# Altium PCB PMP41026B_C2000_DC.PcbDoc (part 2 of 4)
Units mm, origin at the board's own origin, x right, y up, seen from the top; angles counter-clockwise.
Board outline 100 x 30 mm, 4 copper layers (Top Layer, Layer2-Plane, Layer3-Plane, Bottom Layer), stack 1.565 mm thick; 260 components, 175 nets, 797 pads, 279 vias.
Unrouted connection lines stored in the file: 19.
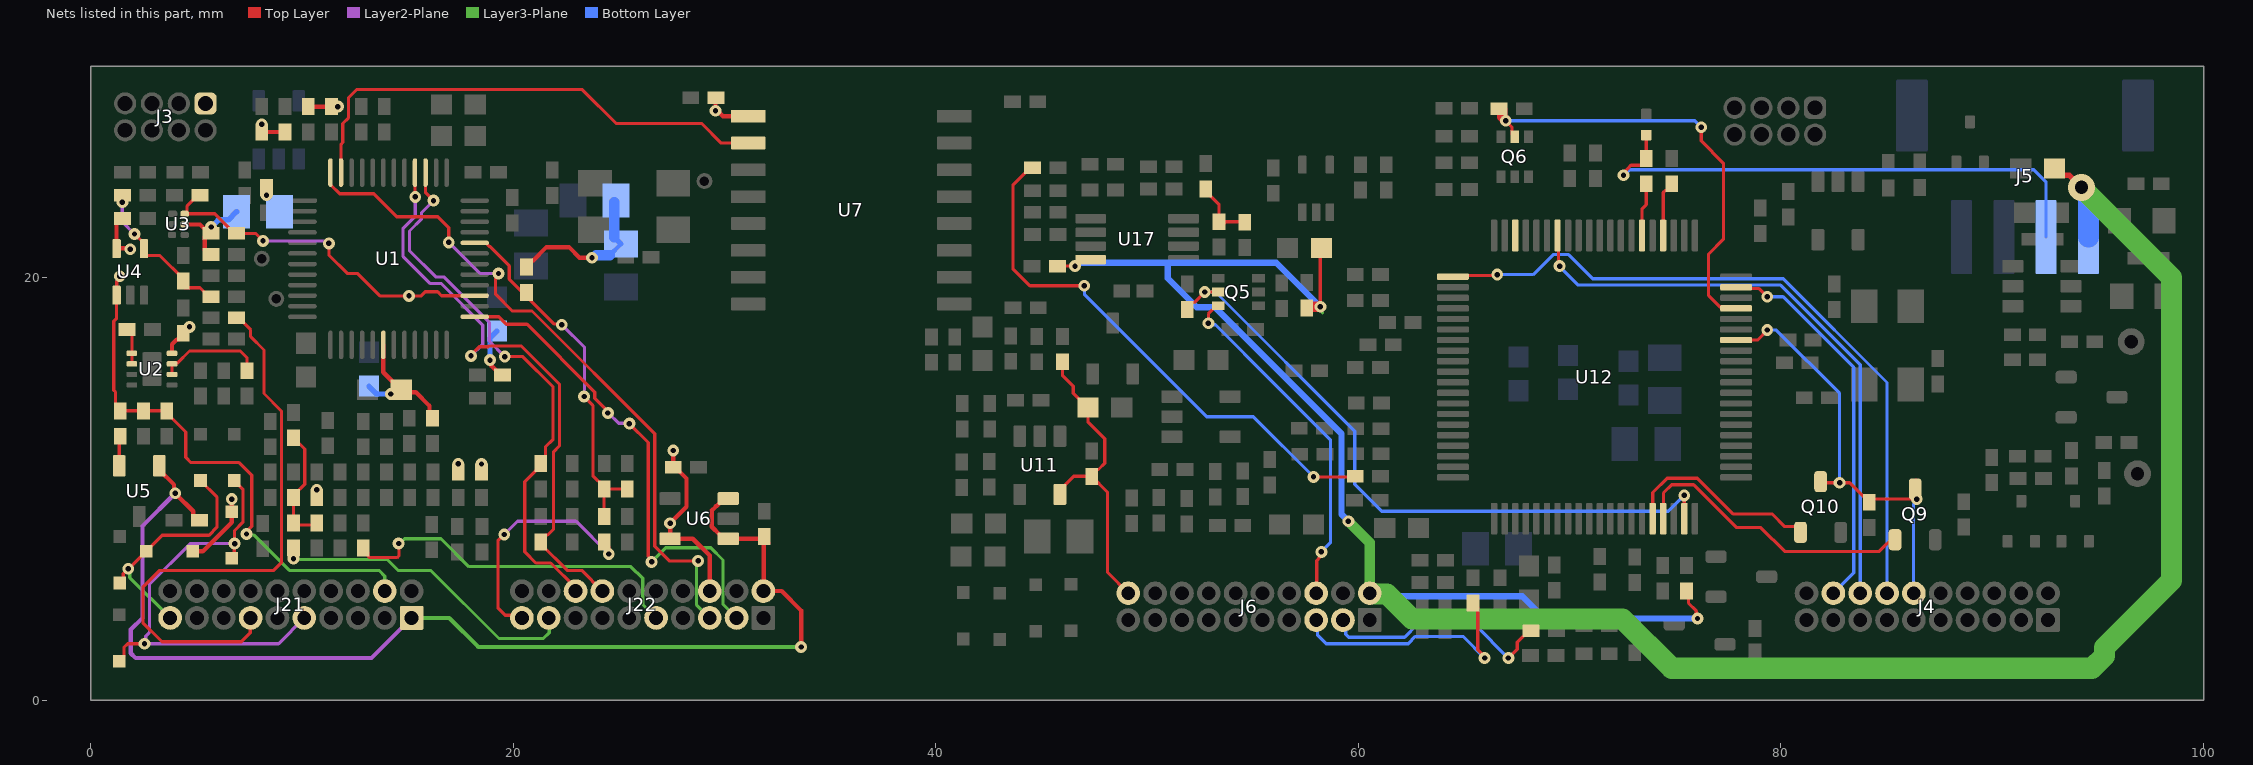
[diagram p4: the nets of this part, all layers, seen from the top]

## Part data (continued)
C2 C3 C4 C5 C71 C73 C74 C75 C76 C77 C79: library part CMP-0006320-2, "CAP, CERM, 470 pF, 50 V, +/- 10%, X7R, AEC-Q200 Grade 1, 0402", Cap_Case=0402, Manufacturer=TDK, Supplier Part Number 1=445-6888-1-ND, TempCo=X7R, Tolerance_%=10%, Value1="4.96489 ohm", Value2=50V, ValueDisplayed=470pF
C6 C9 C14 C15: library part CMP-0006531-2, "CAP, CERM, 0.1 uF, 6.3 V, +/- 10%, X5R, 0402", Cap_Case=0402, Manufacturer=MuRata, Supplier Part Number 1=GRM155R60J104KA01D-ND, TempCo=X5R, Tolerance_%=10%, Value1=Unknown, Value2=6.3V, ValueDisplayed=0.1uF
C7: library part CMP-0006266-2, "CAP, CERM, 0.047 uF, 10 V, +/- 10%, X5R, 0402", Cap_Case=0402, Manufacturer=TDK, Supplier Part Number 1=445-4980-1-ND, TempCo=X5R, Tolerance_%=10%, Value1=Unknown, Value2=10V, ValueDisplayed=0.047uF
C8: library part CMP-0064911-2, "CAP, CERM, 10 pF, 50 V,+/- 2.5%, C0G/NP0, AEC-Q200 Grade 1, 0402", Cap_Case=0402, Manufacturer=AVX, Supplier Part Number 1=478-5991-1-ND, TempCo=C0G/NP0, Tolerance_%=2.5%, Value1=Unknown, Value2=50V, ValueDisplayed=10pF
C10 C12 C17: library part CMP-0006560-2, "CAP, CERM, 1000 pF, 10 V, +/- 10%, X5R, 0402", Cap_Case=0402, Manufacturer=MuRata, Supplier Part Number 1=GRM155R61A102KA01D-ND, TempCo=X5R, Tolerance_%=10%, Value1=Unknown, Value2=10V, ValueDisplayed=1000pF
C11 C20 C21 C25 C26 C27 C28 C100: library part CMP-0006629-2, "CAP, CERM, 0.1 uF, 10 V, +/- 10%, X7R, 0402", Cap_Case=0402, Manufacturer=MuRata, Supplier Part Number 1=GRM155R71A104KA01D-ND, TempCo=X7R, Tolerance_%=10%, Value1=Unknown, Value2=10V, ValueDisplayed=0.1uF
C13: library part CMP-0006351-2, "CAP, CERM, 0.1 uF, 16 V, +/- 10%, X7R, 0402", Cap_Case=0402, Manufacturer=MuRata, Supplier Part Number 1=490-4759-2-ND, TempCo=X7R, Tolerance_%=10%, Value1=Unknown, Value2=16V, ValueDisplayed=0.1uF
C16: library part CMP-0064967-2, "CAP, CERM, 0.47 uF, 10 V,+/- 10%, X7S, 0402", Cap_Case=0402, Manufacturer=MuRata, Supplier Part Number 1=490-14427-1-ND, TempCo=X7S, Tolerance_%=10%, Value1=Unknown, Value2=10V, ValueDisplayed=0.47uF
C18 C19 C38 C43: library part CMP-0007318-5, "CAP, CERM, 10 uF, 10 V, +/- 20%, X5R, 0603", Cap_Case=0603, Manufacturer=MuRata, TempCo=X5R, Tolerance_%=20%, Value1=Unknown, Value2=10V, ValueDisplayed=10uF
C22: library part CMP-0006623-2, "CAP, CERM, 0.1 uF, 6.3 V, +/- 10%, X7R, 0402", Cap_Case=0402, Manufacturer=MuRata, Supplier Part Number 1=GRM155R70J104KA01D-ND, TempCo=X7R, Tolerance_%=10%, Value1=Unknown, Value2=6.3V, ValueDisplayed=0.1uF
C23 C63: library part CMP-0006641-2, "CAP, CERM, 0.1 uF, 16 V, +/- 10%, X7R, 0402", Cap_Case=0402, Manufacturer=MuRata, Supplier Part Number 1=490-3261-1-ND, TempCo=X7R, Tolerance_%=10%, Value1=Unknown, Value2=16V, ValueDisplayed=0.1uF
C29 C37: library part CMP-0006691-2, "CAP, CERM, 470 pF, 50 V, +/- 10%, X7R, 0402", Cap_Case=0402, Manufacturer=MuRata, Supplier Part Number 1=490-1300-1-ND, TempCo=X7R, Tolerance_%=10%, Value1=Unknown, Value2=50V, ValueDisplayed=470pF
C30 C48 C49 C50 C51 C52 C53 C54 C55 C70: library part CMP-0006221-2, "CAP, CERM, 0.1 uF, 10 V, +/- 20%, X5R, 0402", Cap_Case=0402, Manufacturer="Wurth Elektronik", Supplier Part Number 1=732-7487-1-ND, TempCo=X5R, Tolerance_%=20%, Value1=Unknown, Value2=10V, ValueDisplayed=0.1uF
C31: library part CMP-0006699-2, "CAP, CERM, 1000 pF, 100 V, +/- 10%, X7R, 0402", Cap_Case=0402, Manufacturer=MuRata, Supplier Part Number 1=GRM155R72A102KA01D-ND, TempCo=X7R, Tolerance_%=10%, Value1=Unknown, Value2=100V, ValueDisplayed=1000pF
C32 C66 C69: library part CMP-0007404-4, "CAP, CERM, 0.1 uF, 25 V, +/- 10%, X7R, 0603", Cap_Case=0603, Manufacturer=MuRata, Supplier Part Number 1=490-1524-1-ND, TempCo=X7R, Tolerance_%=10%, Value1=Unknown, Value2=25V, ValueDisplayed=0.1uF
C33 C36 CC1 CC2: library part CMP-0006216-2, "CAP, CERM, 15 pF, 50 V, +/- 5%, C0G/NP0, 0402", Cap_Case=0402, Manufacturer="Wurth Elektronik", Supplier Part Number 1=710-885012005056, TempCo=C0G/NP0, Tolerance_%=5%, Value1=Unknown, Value2=50V, ValueDisplayed=15pF
C34 C35: library part CMP-0007048-4, "CAP, CERM, 0.33 uF, 50 V, +/- 10%, X7R, 0603", Cap_Case=0603, Manufacturer=TDK, Supplier Part Number 1=445-5950-1-ND, TempCo=X7R, Tolerance_%=10%, Value1="0.016574 ohm", Value2=50V, ValueDisplayed=0.33uF
C39 C46 C72: library part CMP-0006833-4, "CAP, CERM, 1 uF, 25 V, +/- 10%, X7R, 0603", Cap_Case=0603, Manufacturer="Wurth Elektronik", Supplier Part Number 1=732-7994-1-ND, TempCo=X7R, Tolerance_%=10%, Value1=Unknown, Value2=25V, ValueDisplayed=1uF
C40: library part CMP-0006305-2, "CAP, CERM, 100 pF, 50 V, +/- 10%, X7R, 0402", Cap_Case=0402, Manufacturer="Yageo America", Supplier Part Number 1=311-1419-1-ND, TempCo=X7R, Tolerance_%=10%, Value1=Unknown, Value2=50V, ValueDisplayed=100pF(DNP)
C41 C44 C47: library part CMP-0860555-1, "CAP, CERM, 0.1 µF, 25 V,+/- 10%, X7R, 0402", Cap_Case=0402, Manufacturer=Yageo, TempCo=X7R, Tolerance_%=10%, Value2=25V, ValueDisplayed=0.1µF
C42 CP1 CP2: library part CMP-0008395-2, "CAP, CERM, 10 uF, 10 V, +/- 10%, X5R, 0805", Cap_Case=0805, Manufacturer="Taiyo Yuden", Supplier Part Number 1=05X8343, TempCo=X5R, Tolerance_%=10%, Value1=Unknown, Value2=10V, ValueDisplayed=10uF
C45: library part CMP-0006658-2, "CAP, CERM, 0.01 uF, 25 V, +/- 10%, X7R, 0402", Cap_Case=0402, Manufacturer=MuRata, Supplier Part Number 1=490-1312-1-ND, TempCo=X7R, Tolerance_%=10%, Value1=Unknown, Value2=25V, ValueDisplayed=0.01uF
C56 C58 C59 CP3 CP4: library part CMP-0007091-5, "CAP, CERM, 2.2 uF, 10 V, +/- 10%, X5R, AEC-Q200 Grade 3, 0603", Cap_Case=0603, Manufacturer=TDK, Supplier Part Number 1=445-12444-1-ND, TempCo=X5R, Tolerance_%=10%, Value1=Unknown, Value2=10V, ValueDisplayed=2.2uF
C57 C64 C65 C67: library part CMP-0006200-2, "CAP, CERM, 100 pF, 16 V, +/- 10%, X7R, 0402", Cap_Case=0402, Manufacturer=AVX, Supplier Part Number 1=478-7887-1-ND, TempCo=X7R, Tolerance_%=10%, Value1=Unknown, Value2=16V, ValueDisplayed=100pF
C60 C61: library part CMP-0006352-2, "CAP, CERM, 0.01 uF, 25 V, +/- 10%, X7R, 0402", Cap_Case=0402, Manufacturer=MuRata, Supplier Part Number 1=490-6043-2-ND, TempCo=X7R, Tolerance_%=10%, Value1=Unknown, Value2=25V, ValueDisplayed=0.01uF
C62: library part CMP-0007499-4, "CAP, CERM, 2.2 uF, 16 V, +/- 10%, X7R, 0603", Cap_Case=0603, Manufacturer=MuRata, Supplier Part Number 1=81-GRM188Z71C225KE3D, TempCo=X7R, Tolerance_%=10%, Value1=Unknown, Value2=16V, ValueDisplayed=2.2uF
C68: library part CMP-0092424-1, "Cap Cer 3300pF 50V X7R 0402", Digikey Part Number=732-7559-1-ND, Manufacturer="Wurth Electronics", Mouser Part Number=710-885012205064, Operating Temperature Range="-55°C to +125°C", TempCo=15%, Temperature Characteristic=X7R, Tolerance_%=10%, ValueDisplayed=3.3nF
D1 D2 DC1 DC2 DC3 DC4: library part CMP-0028573-2, "Diode, Schottky, 40 V, 0.03 A, SOD-323", Manufacturer="Diodes Inc.", Value1=0.03A, Value2=1V
D3 D4 D5 D6: library part CMP-0029006-1, "Diode, Ultrafast, 100 V, 0.25 A, SOD-323", Manufacturer=Nexperia, Supplier Part Number 1=568-5003-1-ND, Value1=0.25A, Value2=1.4V
D8 D13: library part CMP-0002951-3, "LED, Red, SMD", Color=Red, Manufacturer="Wurth Elektronik", Power_TotalModule=72mW, Value1=0.072W, Value2=1.9V
D9 D10: library part CMP-0076979-3, "Diode, Switching, 100 V, 0.25 A, SOD-523", Manufacturer=Nexperia, Value1=0.25A, Value2=1.25V
D11 D12: library part CMP-0076926-2, "Diode, Switching, 100 V, 0.15 A, SOT-323", Manufacturer=Nexperia, Value1=0.15A, Value2=1.25V
J3 J7: library part CMP-0086278-1, "Header, 1.27mm, 4x2, Gold, R/A, TH", Current_A=1A, Manufacturer="Sullins Connector Solutions", Voltage_V=500V
J4 J6 J21 J22: library part CMP-0122579-1, "Connector Header Through Hole, Right Angle 20 position 0.050\" (1.27mm)", Current_A=1A, Digikey Part Number=952-1398-ND, Manufacturer=Harwin, Mouser Part Number=855-M50-3901042, Operating Temperature Range="-40°C to +105°C"
J5: library part CMP-0123064-1, "Connector Header, PH Series, 4 Position, Side Entry, 2.00mm, Solder, Surface Mount, Natural.", Current_A=2A, Digikey Part Number=455-S4B-PH-SM4-TBCT-ND, Manufacturer=JST, Operating Temperature Range="-25°C to +85°C", Voltage_V=100V
L1 LP1: library part CMP-0003363-1, "Ferrite Bead, 220 ohm @ 100 MHz, 2 A, 0805", Manufacturer=MuRata, Supplier Part Number 1=490-1054-1-ND, Value1="0.045 ohm", Value2=2A, ValueDisplayed="220 ohm"
L2 LP2: library part CMP-0003093-1, "Ferrite Bead, 60 ohm @ 100 MHz, 3 A, 0805", Manufacturer="Wurth Elektronik", Supplier Part Number 1=732-1612-1-ND, Value1="0.025 ohm", Value2=3A, ValueDisplayed="60 ohm"
Logo1: library part CMP-0074838-1, "Texas Instrument Corporate Signature", PartNumber="Texas Instruments"
Q5 Q6: library part CMP-0000770-1, "MOSFET, 2-CH, N-CH, 60 V, 0.115 A, SOT-363", Alternate Manufacturer=None, Manufacturer="Fairchild Semiconductor", Supplier Part Number 1=2N7002DWCT-ND
Q7 Q8 Q10 Q12: library part CMP-0000388-2, "Transistor, NPN, 40 V, 0.15 A, SOT-23", Manufacturer="Diodes Inc.", Supplier Part Number 1=MMBT4401-FDICT-ND, Value1="0.15 A", Value2=300
Q9: library part CMP-0000327-2, "Transistor, PNP, 40 V, 0.6 A, SOT-23", Manufacturer="Fairchild Semiconductor", Supplier Part Number 1=MMBT4403FSCT-ND, Value1="0.6 A", Value2=500
Q11: library part CMP-0000776-1, "MOSFET, N-CH, 60 V, 0.115 A, SOT-323", Alternate Manufacturer=None, Manufacturer="Diodes Inc.", Supplier Part Number 1=2N7002W-FDICT-ND, Value1=7
R1 R2 R3 R4 R40 R49 R62 R63 R68 R70 R76 R78 R95 R113: library part CMP-0025958-3, "RES, 10.0 k, 1%, 0.063 W, AEC-Q200 Grade 0, 0402", Manufacturer=Vishay-Dale, Power_W=63mW, Supplier Part Number 1=541-10.0KLCT-ND, TempCo="100 ppm/C", Tolerance_%=1%, Value2=0.063W, Value_Code=10k0, ValueDisplayed=10.0k
R5 R6 R7 R8 R10 R11 R31 R32 R66 R67 R77 R101 R102 R103 R104: library part CMP-0026822-3, "RES, 0, 5%, 0.063 W, AEC-Q200 Grade 0, 0402", Manufacturer=Vishay-Dale, Power_W=63mW, Supplier Part Number 1=541-0.0JCT-ND, TempCo="200 ppm/C", Tolerance_%=5%, Value2=0.063W, Value_Code=0000, ValueDisplayed=0
R9: library part CMP-0026874-3, "RES, 200, 5%, 0.063 W, AEC-Q200 Grade 0, 0402", Manufacturer=Vishay-Dale, Power_W=63mW, Supplier Part Number 1=541-200JCT-ND, TempCo="200 ppm/C", Tolerance_%=5%, Value2=0.063W, Value_Code=200R, ValueDisplayed=200
R12: library part CMP-0026781-1, "RES, 4.87 k, 0.1%, 0.062 W, AEC-Q200 Grade 0, 0402", Manufacturer=Panasonic, Power_W=62mW, Supplier Part Number 1=P4.87KDCCT-ND, TempCo="25 ppm/C", Tolerance_%=0.1%, Value2=0.062W, Value_Code=4k87, ValueDisplayed=4.87k
R13 R14: library part CMP-0025959-3, "RES, 10.2 k, 1%, 0.063 W, AEC-Q200 Grade 0, 0402", Manufacturer=Vishay-Dale, Power_W=63mW, Supplier Part Number 1=541-10.2KLCT-ND, TempCo="100 ppm/C", Tolerance_%=1%, Value2=0.063W, Value_Code=10k2, ValueDisplayed=10.2k
R15 R16 R17 R18 R19 R23 R24 R29 R30 R38 R73 R74 R90 R91 R92 R93 R98: library part CMP-0026825-5, "RES, 10 k, 5%, 0.063 W, AEC-Q200 Grade 0, 0402", Manufacturer=Vishay-Dale, Power_W=63mW, Supplier Part Number 1=541-10KJCT-ND, TempCo="200 ppm/C", Tolerance_%=5%, Value2=0.063W, Value_Code=10k0, ValueDisplayed=10k
R20 R26 R42: library part CMP-0026179-2, "RES, 22.6 k, 1%, 0.063 W, AEC-Q200 Grade 0, 0402", Manufacturer=Vishay-Dale, Power_W=63mW, Supplier Part Number 1=541-22.6KLCT-ND, TempCo="100 ppm/C", Tolerance_%=1%, Value2=0.063W, Value_Code=22k6, ValueDisplayed=22.6k
R21 R25 R33: library part CMP-0026952-5, "RES, 5.6 k, 5%, 0.063 W, AEC-Q200 Grade 0, 0402", Manufacturer=Vishay-Dale, Power_W=63mW, Supplier Part Number 1=541-5.6KJCT-ND, TempCo="200 ppm/C", Tolerance_%=5%, Value2=0.063W, Value_Code=5k60, ValueDisplayed=5.6k
R22 R27 R34: library part CMP-0026555-2, "RES, 7.50 k, 1%, 0.063 W, AEC-Q200 Grade 0, 0402", Manufacturer=Vishay-Dale, Power_W=63mW, Supplier Part Number 1=541-7.50KLCT-ND, TempCo="100 ppm/C", Tolerance_%=1%, Value2=0.063W, Value_Code=7k50, ValueDisplayed=7.50k
R28 R36: library part CMP-0026591-2, "RES, 8.66 k, 1%, 0.063 W, AEC-Q200 Grade 0, 0402", Manufacturer=Vishay-Dale, Power_W=63mW, Supplier Part Number 1=541-8.66KLCT-ND, TempCo="100 ppm/C", Tolerance_%=1%, Value2=0.063W, Value_Code=8k66, ValueDisplayed=8.66k
R35 R37 R61 R65: library part CMP-0026890-5, "RES, 2.2 k, 5%, 0.063 W, AEC-Q200 Grade 0, 0402", Manufacturer=Vishay-Dale, Power_W=63mW, Supplier Part Number 1=541-2.2KJCT-ND, TempCo="200 ppm/C", Tolerance_%=5%, Value2=0.063W, Value_Code=2k20, ValueDisplayed=2.2k
R39 R69 R106 R110: library part CMP-0026463-2, "RES, 5.11 k, 1%, 0.063 W, AEC-Q200 Grade 0, 0402", Manufacturer=Vishay-Dale, Power_W=63mW, Supplier Part Number 1=541-5.11KLCT-ND, TempCo="100 ppm/C", Tolerance_%=1%, Value2=0.063W, Value_Code=5k11, ValueDisplayed=5.11k
R41: library part CMP-0026213-2, "RES, 27.4 k, 1%, 0.063 W, AEC-Q200 Grade 0, 0402", Manufacturer=Vishay-Dale, Power_W=63mW, Supplier Part Number 1=541-27.4KLCT-ND, TempCo="100 ppm/C", Tolerance_%=1%, Value2=0.063W, Value_Code=27k4, ValueDisplayed=27.4k
R43 R82 R88 R105: library part CMP-0026745-1, "RES, 100 k, 1%, 0.063 W, 0402", Manufacturer="Samsung Electro-Mechanics", Power_W=63mW, Supplier Part Number 1=1276-3432-1-ND, TempCo="100 ppm/C", Tolerance_%=1%, Value2=0.063W, Value_Code=100k
R44: library part CMP-0026677-1, "RES, 200 k, 1%, 0.1 W, 0402", Manufacturer=Panasonic, Power_W=100mW, Supplier Part Number 1=P200KLCT-ND, TempCo="100 ppm/C", Tolerance_%=1%, Value2=0.1W, Value_Code=200k
R45 R54: library part CMP-0026979-3, "RES, 820, 5%, 0.063 W, AEC-Q200 Grade 0, 0402", Manufacturer=Vishay-Dale, Power_W=63mW, Supplier Part Number 1=541-820JCT-ND, TempCo="200 ppm/C", Tolerance_%=5%, Value2=0.063W, Value_Code=820R, ValueDisplayed=820
R46: library part CMP-0026722-1, "RES, 100, 1%, 0.063 W, 0402", Manufacturer="Yageo America", Power_W=63mW, Supplier Part Number 1=311-100LRCT-ND, TempCo="100 ppm/C", Tolerance_%=1%, Value2=0.063W, Value_Code=100R, ValueDisplayed=DNP
R47 R59: library part CMP-0026240-2, "RES, 2.67 k, 1%, 0.063 W, AEC-Q200 Grade 0, 0402", Manufacturer=Vishay-Dale, Power_W=63mW, Supplier Part Number 1=541-2.67KLCT-ND, TempCo="100 ppm/C", Tolerance_%=1%, Value2=0.063W, Value_Code=2k67, ValueDisplayed=2.67k
R48: library part CMP-0025958-3, "RES, 10.0 k, 1%, 0.063 W, AEC-Q200 Grade 0, 0402", Manufacturer=Vishay-Dale, Power_W=63mW, Supplier Part Number 1=541-10.0KLCT-ND, TempCo="100 ppm/C", Tolerance_%=1%, Value2=0.063W, Value_Code=10k0, ValueDisplayed=DNP
R50 R64 R75 R80 R81 R83 R114 R116 R117: library part CMP-0026722-1, "RES, 100, 1%, 0.063 W, 0402", Manufacturer="Yageo America", Power_W=63mW, Supplier Part Number 1=311-100LRCT-ND, TempCo="100 ppm/C", Tolerance_%=1%, Value2=0.063W, Value_Code=100R, ValueDisplayed=100
R51 R57: library part CMP-0026437-2, "RES, 51.1 k, 1%, 0.063 W, AEC-Q200 Grade 0, 0402", Manufacturer=Vishay-Dale, Power_W=63mW, Supplier Part Number 1=541-51.1KLCT-ND, TempCo="100 ppm/C", Tolerance_%=1%, Value2=0.063W, Value_Code=51k1, ValueDisplayed=51.1k
R52: library part CMP-0020812-2, "RES, 2.2, 5%, 0.125 W, 0805", Manufacturer="Yageo America", Power_W=125mW, Supplier Part Number 1=311-2.2ARCT-ND, TempCo="200 ppm/C", Tolerance_%=5%, Value2=0.125W, Value_Code=2R20, ValueDisplayed=DNP
R53 R108 R109 R112: library part CMP-0026657-1, "RES, 1.00 k, 1%, 0.1 W, 0402", Manufacturer=Panasonic, Power_W=100mW, Supplier Part Number 1=P1.00KLCT-ND, TempCo="100 ppm/C", Tolerance_%=1%, Value2=0.1W, Value_Code=1k00, ValueDisplayed=1.00k
R55 R56: library part CMP-0026863-2, "RES, 1.5 M, 5%, 0.063 W, AEC-Q200 Grade 0, 0402", Manufacturer=Vishay-Dale, Power_W=63mW, Supplier Part Number 1=541-1.5MJCT-ND, TempCo="200 ppm/C", Tolerance_%=5%, Value2=0.063W, Value_Code=1M50, ValueDisplayed=1.5M
R58 R60: library part CMP-0026949-3, "RES, 56 k, 5%, 0.063 W, AEC-Q200 Grade 0, 0402", Manufacturer=Vishay-Dale, Power_W=63mW, Supplier Part Number 1=541-56KJCT-ND, TempCo="200 ppm/C", Tolerance_%=5%, Value2=0.063W, Value_Code=56k0, ValueDisplayed=56k
R71 R111: library part CMP-0026725-1, "RES, 1.00 k, 1%, 0.0625 W, 0402", Manufacturer="Yageo America", Power_W=62.5mW, Supplier Part Number 1=311-1.00KLRCT-ND, TempCo="100 ppm/C", Tolerance_%=1%, Value2=0.0625W, Value_Code=1k00, ValueDisplayed=1.00k
R72: library part CMP-0026943-2, "RES, 510 k, 5%, 0.063 W, AEC-Q200 Grade 0, 0402", Manufacturer=Vishay-Dale, Power_W=63mW, Supplier Part Number 1=541-510KJCT-ND, TempCo="200 ppm/C", Tolerance_%=5%, Value2=0.063W, Value_Code=510k
R85: library part CMP-0026663-1, "RES, 120 k, 1%, 0.1 W, AEC-Q200 Grade 0, 0402", Manufacturer=Panasonic, Power_W=100mW, Supplier Part Number 1=P120KLCT-ND, TempCo="100 ppm/C", Tolerance_%=1%, Value2=0.1W, Value_Code=120k
R87: library part CMP-0026717-1, "RES, 10.0, 1%, 0.063 W, 0402", Manufacturer=Rohm, Power_W=63mW, Supplier Part Number 1=RHM10.0LCT-ND, TempCo="100 ppm/C", Tolerance_%=1%, Value2=0.063W, Value_Code=10R0, ValueDisplayed=10.0
R89: library part CMP-0026164-2, "RES, 20.0, 1%, 0.063 W, AEC-Q200 Grade 0, 0402", Manufacturer=Vishay-Dale, Power_W=63mW, Supplier Part Number 1=541-20.0LCT-ND, TempCo="100 ppm/C", Tolerance_%=1%, Value2=0.063W, Value_Code=20R0, ValueDisplayed=20.0
R94: library part CMP-0026743-1, "RES, 820, 1%, 0.063 W, 0402", Manufacturer="Yageo America", Power_W=63mW, Supplier Part Number 1=311-820LRCT-ND, TempCo="100 ppm/C", Tolerance_%=1%, Value2=0.063W, Value_Code=820R, ValueDisplayed=820
R96 R99: library part CMP-0026178-2, "RES, 22.1 k, 1%, 0.063 W, AEC-Q200 Grade 0, 0402", Manufacturer=Vishay-Dale, Power_W=63mW, Supplier Part Number 1=541-22.1KLCT-ND, TempCo="100 ppm/C", Tolerance_%=1%, Value2=0.063W, Value_Code=22k1, ValueDisplayed=22.1k
R97: library part CMP-0026227-2, "RES, 2.00 k, 1%, 0.063 W, AEC-Q200 Grade 0, 0402", Manufacturer=Vishay-Dale, Power_W=63mW, Supplier Part Number 1=541-2.00KLCT-ND, TempCo="100 ppm/C", Tolerance_%=1%, Value2=0.063W, Value_Code=2k00, ValueDisplayed=2.00k
R100: library part CMP-0026950-3, "RES, 56, 5%, 0.063 W, AEC-Q200 Grade 0, 0402", Manufacturer=Vishay-Dale, Power_W=63mW, Supplier Part Number 1=541-56JCT-ND, TempCo="200 ppm/C", Tolerance_%=5%, Value2=0.063W, Value_Code=56R0, ValueDisplayed=56
R107: library part CMP-0026589-2, "RES, 8.25 k, 1%, 0.063 W, AEC-Q200 Grade 0, 0402", Manufacturer=Vishay-Dale, Power_W=63mW, Supplier Part Number 1=541-8.25KLCT-ND, TempCo="100 ppm/C", Tolerance_%=1%, Value2=0.063W, Value_Code=8k25, ValueDisplayed=8.25k
TP1 TP2 TP3: library part CMP-0003719-1, "Testpoint", Manufacturer="Texas Instruments"
TP4 TP5: library part CMP-0078143-3, "TEST POINT.  No entry in BOM.", Manufacturer=N/A
U1: library part CMP-0088708-1, "TMS320F28002x Microcontrollers", Frequency_Fixed=100MHz, Manufacturer="Texas Instruments", Max Supply Voltage=3.63V, Min Supply Voltage=1.14V, Nominal Supply Current=12-86mA, Operating Temperature Range="-40°C to +125°C"
U2: library part CMP-0092447-1, "40-V, dual 4.5MHz, rail-to-rail input/output, low-offset-voltage, low-noise op amp 8-WSON -40 to 125", Digikey Part Number=296-OPA2991IDSGRTR-ND, Input Bias Current=0.00001uA, Input Offset Voltage=0.125mV, Manufacturer="Texas Instruments", Max Dual Supply Voltage=20V, Max Supply Voltage=40V, Min Dual Supply Voltage=1.35V, Min Supply Voltage=2.7V, Mouser Part Number=595-OPA2991IDSGR, Nominal Supply Current=560uA, Operating Temperature Range="-40°C to +125°C", Output Current Per Channel=75mA, Voltage Gain=145dB
U3: library part CMP-0050995-4, "1-Channel, 2:1 Analog Switch, DRY0006A (USON-6)", F @ Nom Voltage(Max)(Mhz)=150, Generic Part Number=SN74LVC1G3157, ICC @ Nom Voltage(Max)(mA)=0.01, Manufacturer="Texas Instruments", Operating Temperature Range="-40 to 125 C", Operating Temperature Range(C)="-40 to 85", Rating=Catalog, tpd @ Nom Voltage(Max)(ns)=2,1.2,0.8,0.3, Voltage(Nom)(V)=1.8,2.5,3.3,5
U4: library part CMP-0092514-1, "General Purpose Amplifier Circuit Rail-to-Rail SC-70-5", Digikey Part Number=296-OPA991IDCKRCT-ND, Input Bias Current=0.00001uA, Input Offset Voltage=0.125mV, Manufacturer="Texas Instruments", Max Dual Supply Voltage=20V, Max Supply Voltage=40V, Min Dual Supply Voltage=1.35V, Min Supply Voltage=2.7V, Mouser Part Number=595-OPA991IDCKR, Nominal Supply Current=560uA, Operating Temperature Range="-40°C to +125°C", Output Current Per Channel=75mA
U5: library part CMP-0032499-1, "3.0 V, 50 ppm / degC, 50 uA Series (Bandgap) Voltage Reference, -40 to 125 degC, 3-pin SOT-23 (DBZ), Green (RoHS & no Sb/Br)", Manufacturer="Texas Instruments", Rating=Catalog, Temp Coeff(Max)(ppm/ degree C)=50, Temp Coeff(Typ)(ppm/ degree C)=20
U6: library part CMP-0066771-1, "150-mA, Low-Dropout Regulator with Foldback Current Limit for Portable Devices, DBV0005A (SOT-23-5)", Alternate Manufacturer="Texas Instruments", Alternate PartNumber=TLV71333PDBVT
U7: library part CMP-0092396-1, "General Purpose Digital Isolator 5000Vrms 6 Channel 100Mbps 85kV/µs CMTI 16-SOIC (0.295\", 7.50mm Width)", Digikey Part Number=296-ISO7762FDWRCT-ND, Manufacturer="Texas Instruments", Max Supply Voltage=5.5V, Min Supply Voltage=2.25V, Mouser Part Number=595-ISO7762FDWR, Nominal Supply Current=2.1-25.7mA, Operating Temperature Range="-55°C to +125°C"
U8 U15: library part CMP-0085635-1, "Data-Line Surge and ESD Protection Diode Array, DBV0005A (SOT-23-5)", Alternate Manufacturer="Texas Instruments", Operating Temperature Range="-40 to 125 C", Rating=Catalog
U9: library part CMP-0073542-1, "TLVx376, 5.5 MHz, Low-Noise, Low Quiescent Current, Precision Operational Amplifiers, DBV0005A (SOT-23-5)", Alternate Manufacturer="Texas Instruments", Alternate PartNumber=TLV376IDBVT
U10: library part CMP-0051789-2, "Dual Buffer/Driver with Open-Drain Output, DBV0006A, LARGE T&R", F @ Nom Voltage(Max)(Mhz)=150, Generic Part Number=SN74LVC2G07, ICC @ Nom Voltage(Max)(mA)=0.01, Manufacturer="Texas Instruments", Operating Temperature Range(C)="-40 to 125", Rating=Catalog, tpd @ Nom Voltage(Max)(ns)=8.6,4.4,3.7,2.9, Voltage(Nom)(V)=1.8,2.5,3.3,5
U11: library part CMP-0861047-2, "50-MHz, Low-Power, Gain of 6-V/V Stable, Rail-to-Rail Output CMOS Operational Amplifier, DBV0005A (SOT-23-5)", Alternate Manufacturer="Texas Instruments"
U12: library part CMP-0121731-1, "Automotive C2000™ 32-bit MCU 120-MHz 384-KB flash, FPU, TMU with CLA, CLB, AES and CAN-FD 80-LQFP -40 to 125", Digikey Part Number=296-F280039CPNQ1-ND, Frequency_Fixed=120MHz, Manufacturer="Texas Instruments", Max Supply Voltage=3.63V, Min Supply Voltage=1.14V, Mouser Part Number=595-F280039CPNQ1, Operating Temperature Range="-40°C to +125°C"
U13: library part CMP-0033081-1, "Low-Voltage Adjustable Precision Shunt Regulator, 80 mA, -40 to 125 degC, 3-pin SOT-23 (DBZ), Green (RoHS & no Sb/Br)", Manufacturer="Texas Instruments", Rating=Catalog, Temp Coeff(Max)(ppm/ degree C)=129
U16: library part CMP-0073339-2, "2.4V, 10µA Temperature Sensor, 5-pin SC-70 Micro SMD, Pb-Free", Manufacturer="Texas Instruments", PackageTopMarking=T2B*XTT, PowerWise=N
U17: library part CMP-0092737-1, "40-V, dual-channel, 4.5-MHz, rail-to-rail input/output, low-offset-voltage, low-noise op amp 8-VSSOP -40 to 125", Input Bias Current=0.00001uA, Input Offset Voltage=0.125mV, Manufacturer="Texas Instruments", Max Dual Supply Voltage=20V, Max Supply Voltage=40V, Min Dual Supply Voltage=1.35V, Min Supply Voltage=2.7V, Mouser Part Number=595-OPA2991IDGKR, Nominal Supply Current=560uA, Operating Temperature Range="-40°C to +125°C", Output Current Per Channel=75mA, Voltage Gain=145dB
Y1 Y2: library part CMP-0080365-2, "Crystal, 20 MHz, 25 ppm, 18 pF, SMD", Frequency Stability="30 ppm", Frequency Tolerance="25 ppm", Frequency_Fixed=20MHz, Load Capacitance="18 pF", Manufacturer="ECS Inc.", Supplier Part Number 1=XC2693CT-ND
ZZ1: library part CMP-0077236-1
ZZ2: library part CMP-0077237-1
ZZ3: library part CMP-0077238-1

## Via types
v1: diameter 0.559, hole 0.254, Top Layer to Bottom Layer, tented both sides, 274 vias
v2: diameter 1.27, hole 0.635, Top Layer to Bottom Layer, tented both sides, 3 vias
v3: diameter 0.559, hole 0.254, Top Layer to Bottom Layer, 2 vias

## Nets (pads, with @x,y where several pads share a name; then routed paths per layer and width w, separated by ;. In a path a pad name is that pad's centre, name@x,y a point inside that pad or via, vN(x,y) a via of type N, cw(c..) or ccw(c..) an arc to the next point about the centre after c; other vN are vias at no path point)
1V65_ref: C17.1 J21.4 R41.2 R42.1 U4.1 | length 25.8
  Top Layer w0.152: U4.1@1.225,19.175 1.225,18.073 1.096,17.945 1.096,14.679 1.176,14.599 1.176,13.924 R41.2@1.4,13.7 R42.1@2.5,13.7 C17.1@3.6,13.7 3.6,13.6 4.5,12.7 4.5,11.5 4.75,11.25 7.025,11.25 7.62,10.655 7.62,8.23 7.375,7.985 v1(7.375,7.875) ; U4.1@1.239,19.202 1.239,19.829 1.375,19.965 v1(1.375,20.075)
  Layer3-Plane w0.152: v1(7.375,7.875) 7.429,7.821 7.735,7.821 9.406,6.15 13.647,6.15 13.92,5.877 J21.4@13.92,5.17
3V0_ref: R41.1 U5.2 | length 1.4
  Top Layer w0.152: U5.2@1.35,11.1 1.35,12.45 R41.1@1.4,12.5
3V3: C22.1 C27.2 CP1.2 CP3.2 J3.1 J22.6 LP1.1 LP2.1 R24.2 R29.1 R30.1 R32.2 R35.1 R37.1 R38.2 U6.5 U7.1 | length 24.7
  Top Layer w0.203: R37.1@7.927,26.7 R37.1@7.963,26.736 ; v1(8.1,27.268) R37.1@8.1,26.9 R38.2@9.2,26.9 ; v1(8.325,23.907) R35.1@8.325,24.275 ; R29.1@10.3,28.1 R30.1@11.4,28.1 v1(11.7,28.1) ; v1(18.9,16.1) 18.958,16.042 18.958,15.842 19.4,15.4 R32.2@19.5,15.4 ; R24.2@20.625,20.5 20.625,20.6 20.823,20.798 20.923,20.798 21.575,21.45 22.639,21.45 23.139,20.95 v1(23.725,20.95) ; U6.5@27.225,7.65 U6.5@27.425,7.65 ; v1(27.575,11.825) C22.1@27.575,11.025 27.675,11.025 28.204,10.496 28.204,9.164 v1(27.425,8.385) U6.5@27.425,7.65 ; J22.6@29.24,5.23 J22.6@29.3,5.17 29.3,6.85 28.5,7.65 U6.5@27.425,7.65 ; C27.2@29.575,28.5 v1(29.575,27.9) 29.671,27.9 29.926,27.645 U7.1@31.125,27.645
  Bottom Layer w0.203: v1(23.725,20.95) 23.821,20.95 v1@23.938,21.067 ; CP1.2@24.567,21.067 CP1.2@25.1,21.6
  Bottom Layer w0.254: v1(18.9,16.1) 18.9,17.15 CP3.2@19.225,17.475 ; CP1.2@24.783,21.917 CP1.2@25.1,21.6 ; LP1.1@24.783,23.567 LP1.1@24.866,23.65
  Bottom Layer w0.5: v1@23.938,21.067 CP1.2@24.567,21.067 ; CP1.2@24.783,21.917 LP1.1@24.783,23.567
3V3A: C11.1 C15.2 C24.2 C100.1 CP4.2 DC1.1 DC2.1 LP2.2 R1.2 R2.2 R3.2 R4.2 R23.2 U1.18 U2.8 U3.5 U4.5 | length 18.6
  Top Layer w0.203: U4.5@1.225,21.375 U4.5@1.225,21.4 ; C15.2@1.5,22.8 1.423,22.8 1.225,22.602 U4.5@1.225,21.4 ; v1(1.875,21.351) 1.826,21.4 U4.5@1.225,21.4 ; U2.8@3.85,16.425 3.85,16.448 3.85,16.855 4.072,17.077 4.177,17.077 4.325,17.225 4.325,17.325 v1(4.675,17.675) ; U3.5@4.45,22.525 5.175,22.525 5.6,22.1 R23.2@5.7,22.1 v1(5.7,22.4) ; DC1.1@4.825,7.05 4.833,7.058 5.311,7.058 6.675,8.422 DC2.1@6.675,8.924 v1(6.675,9.525) ; R23.2@5.402,21.902 5.402,21.298 5.6,21.1 C11.1@5.7,21.1 ; R23.2@5.402,21.902 R23.2@5.451,21.902 ; R4.2@10.7,9.6 v1(10.7,9.968) ; U1.18@13.85,16.825 13.85,15.525 14.675,14.7 C24.2@14.7,14.7 ; v1(14.2,14.5) 14.5,14.5 C24.2@14.7,14.7 ; R1.2@16.175,13.35 16.036,13.489 16.036,13.936 15.386,14.586 14.814,14.586 C24.2@14.7,14.7
  Bottom Layer w0.254: v1(5.7,22.4) 6.042,22.742 6.526,22.742 LP2.2@6.909,23.125 ; CP4.2@13.175,14.875 13.175,14.85 13.523,14.502 13.548,14.502 13.55,14.5 v1(14.2,14.5)
  other v1: 18.5,11.182 17.4,11.2
5V_SEC: C41.1 C46.2 J6.20 R68.1 U11.5 | length 14.8
  Top Layer w0.152: U11.5@45.875,9.75 45.875,9.95 46.525,10.6 C41.1@47.375,10.6 ; R68.1@46,16.025 46,15.363 46.5,14.863 46.5,14.525 47.175,13.85 C46.2@47.2,13.85 47.2,13.175 48,12.375 48,11.225 47.699,10.924 47.599,10.924 47.375,10.7 C41.1@47.375,10.6 ; J6.20@49.11,5.07 48.125,6.055 48.125,9.85 C41.1@47.375,10.6
5Vp: C16.1 C23.1 J21.1 J22.2 U5.1 U6.1 U6.3 | length 56.6
  Top Layer w0.203: U5.1@3.423,10.927 U5.1@3.25,11.1 3.25,10.9 3.942,10.208 3.942,9.858 v1@4.024,9.858 ; v1(4,9.8) 4.068,9.732 4.852,8.948 4.852,8.723 5.05,8.525 C16.1@5.15,8.525 ; U6.3@30.175,9.55 29.975,9.55 29.604,9.179 29.589,9.179 29.396,8.986 29.396,8.214 29.787,7.823 30.002,7.823 U6.1@30.175,7.65 ; U6.1@30.2,7.625 U6.1@30.175,7.65 ; C23.1@32.065,7.46 C23.1@31.875,7.65 ; v1(33.625,2.525) 33.625,4.25 32.705,5.17 J22.2@31.84,5.17 31.857,5.187 31.857,7.633 C23.1@31.875,7.65 ; U6.1@30.175,7.65 31.775,7.65 C23.1@31.875,7.75 C23.1@31.875,7.65
  Layer2-Plane w0.203: v1(4,9.8) 2.45,8.25 2.45,3.9 1.9,3.35 1.9,2.227 2.127,2 13.29,2 J21.1@15.19,3.9
  Layer3-Plane w0.203: J21.1@15.19,3.9 16.975,3.9 18.35,2.525 v1(33.625,2.525)
12VSB: C62.1 C63.1 C66.1 J5.4 J6.2 R91.2 R92.1 U17.8 | length 121.3
  Top Layer w0.152: C63.1@45.75,20.55 v1(46.587,20.55) ; U17.8@46.676,20.639 46.676,20.701 46.825,20.85 U17.8@47.325,20.85 ; R91.2@57.55,18.575 R91.2@57.6,18.625 ; v1(58.2,18.625) 58.2,21.275 C62.1@58.25,21.325 ; R92.1@75.401,4.975 75.501,4.975 75.625,4.851 75.625,4.6 75.993,4.232 75.993,3.932 v1(76.05,3.875)
  Top Layer w0.254: C66.1@92.95,25.175 93.265,24.86 93.64,24.86 v2(94.225,24.275)
  Top Layer w0.5: R91.2@57.6,18.625 v1(58.2,18.625)
  Layer3-Plane w0.152: v1(58.2,18.625) 58.278,18.547 58.278,18.36 58.305,18.333
  Layer3-Plane w0.5: v1(59.525,8.475) 60.54,7.46 J6.2@60.54,5.07
  Layer3-Plane w1: J6.2@60.54,5.07 60.563,5.047 60.648,5.047 60.657,5.038 61.351,5.038 62.539,3.85 72.5,3.85 74.834,1.516 94.727,1.516 95.313,2.102 95.313,2.508 98.484,5.68 98.484,20.016 v2(94.225,24.275)
  Bottom Layer w0.152: J6.2@60.54,5.07 J6.2@60.685,4.925
  Bottom Layer w0.3: v1(46.587,20.55) 46.657,20.55 46.814,20.707 50.975,20.707 ; v1(58.2,18.625) 56.118,20.707 50.975,20.707 ; v1(59.525,8.475) 59.2,8.8 59.2,12.614 53.212,18.602 52.353,18.602 50.975,19.98 50.975,20.707 ; J6.2@60.685,4.925 67.75,4.925 68.8,3.875 v1(76.05,3.875)
  Bottom Layer w1: v2(94.225,24.275) 94.225,24.202 94.55,23.877 J5.4@94.55,21.925
54V_LS: J6.6 Q5.6 | length 16.7
  Top Layer w0.152: v1(52.9,17.85) 52.9,18.29 53.285,18.675 Q5.6@53.375,18.675 ; J6.6@58,5.07 58.025,5.095 58.025,6.615 58.172,6.762 58.172,6.947 v1(58.25,7.025)
  Bottom Layer w0.152: v1(52.9,17.85) 52.977,17.773 53.237,17.773 55.956,15.054 58.675,12.335 58.675,7.45 v1(58.25,7.025)
\54VLS-EN: Q5.5 R98.1 U12.39 | length 31.8
  Top Layer w0.152: R98.1@51.9,18.5 51.9,18.6 52.124,18.824 52.224,18.824 v1(52.725,19.325) Q5.5@53.375,19.325 ; U12.39@75.425,8.6 v1(75.425,9.7)
  Bottom Layer w0.152: v1(52.725,19.325) 53.235,19.325 59.825,12.735 59.825,10.225 61.1,8.95 74.675,8.95 v1(75.425,9.7)
\SMB_ALERT-1: Q6.2 R88.2 U12.57 | length 21.3
  Top Layer w0.152: v1(66.974,27.426) 67.266,27.134 67.266,26.809 Q6.2@67.4,26.675 ; v1(76.225,27.125) 76.225,26.475 77.275,25.425 77.275,21.825 76.575,21.125 76.575,19.156 77.107,18.624 77.801,18.624 U12.57@77.875,18.55
  Top Layer w0.5: R88.2@66.65,28 66.75,28 66.8,27.95 66.8,27.616 66.974,27.442 v1(66.974,27.426)
  Bottom Layer w0.152: v1(66.974,27.426) 75.924,27.426 v1(76.225,27.125)
AC_CUR_SENSE: J21.13 R39.1 | length 27.6
  Top Layer w0.152: R39.1@6.9,18.1 7,18.1 7.567,17.533 7.567,17.215 8.203,16.58 8.203,14.52 9.029,13.695 9.029,7.905 9.029,6.504 8.675,6.15 3.275,6.15 2.475,5.35 2.475,3.675 3.375,2.775 7.125,2.775 7.551,3.201 7.551,3.881 J21.13@7.57,3.9
ACL_SENSE: D1.2 DC1.2 DC3.1 J21.19 | length 12
  Top Layer w0.152: 1.559,5.984 1.559,5.734 DC3.1@1.375,5.55 1.547,5.722 1.547,5.997 v1(1.775,6.225) ; v1@1.787,6.212 DC1.2@2.625,7.05 3.392,7.817 5.603,7.817 5.975,8.189 5.975,9.625 D1.2@5.2,10.4
  Layer3-Plane w0.152: v1(1.775,6.225) 1.853,6.147 1.853,5.807 J21.19@3.76,3.9
ACL_SNS_RECT: R7.2 U2.1 U2.2 | length 1.7
  Top Layer w0.152: R7.2@1.725,17.55 1.95,17.326 U2.2@1.95,15.925
ACN_SENSE: D2.2 DC2.2 DC4.1 J21.9 | length 21.8
  Top Layer w0.152: DC4.1@1.35,1.85 1.574,2.074 1.574,2.499 1.75,2.675 v1(2.55,2.675) ; DC2.2@6.8,6.58 v1@6.8,7.425 ; D2.2@6.8,10.4 7.204,9.996 7.204,8.429 6.813,8.038 v1(6.813,7.416)
  Top Layer w0.254: J21.9@10.055,3.845 J21.9@10.11,3.9
  Layer2-Plane w0.152: 3.819,2.675 v1(2.55,2.675) 2.607,2.732 2.607,3.032 2.78,3.205 2.78,5.48 4.716,7.416 v1(6.813,7.416) ; 3.834,2.675 8.885,2.675 ; 8.896,2.686 J21.9@10.11,3.9
ACN_SNS_RECT: R6.2 U2.6 U2.7 | length 5.1
  Top Layer w0.152: U2.6@3.85,15.425 U2.7@3.85,15.925 3.899,15.974 4.119,15.974 4.679,16.533 7.086,16.533 7.4,16.219 R6.2@7.4,15.6
AD_IBUS: R76.2 R80.2 R99.1 | length 3.1
  Top Layer w0.152: R76.2@52.775,24.2 52.775,24.1 53.4,23.475 R99.1@53.4,22.65 R99.1@53.675,22.65 ; R99.1@53.675,22.6 R99.1@53.675,22.65 ; R80.2@54.625,22.625 54.6,22.65 R99.1@53.675,22.65
ADDR_A0: J6.3 R83.2 | length 11.2
  Top Layer w0.152: v1(67.1,2) 67.521,2.421 67.521,2.746 68.075,3.3 R83.2@68.175,3.3
  Bottom Layer w0.152: J6.3@59.27,3.8 59.403,3.667 59.403,3.122 59.539,2.986 62.186,2.986 62.775,3.575 65.525,3.575 v1(67.1,2)
ADDR_A1: J4.14 U12.1 | length 33.5
  Top Layer w0.152: U12.1@64.475,20.05 64.525,20.1 66.525,20.1 v1(66.575,20.15)
  Bottom Layer w0.152: v1(66.575,20.15) 68.268,20.15 69.214,21.095 69.949,21.095 71.089,19.955 80.107,19.955 85.02,15.042 J4.14@85.02,5.07
BB_CS: J22.9 R5.2 | length 17.1
  Top Layer w0.152: R5.2@12.9,7.2 13.124,6.976 13.124,6.844 13.213,6.755 14.505,6.755 14.594,6.844 14.594,7.406 v1(14.575,7.425)
  Layer3-Plane w0.152: v1(14.575,7.425) 14.642,7.425 14.867,7.65 16.581,7.65 17.901,6.33 25.57,6.33 26.125,5.775 26.125,4.535 J22.9@26.76,3.9
BB_ONOFF: J22.3 U1.25 | length 23.5
  Top Layer w0.152: U1.25@18.175,18.15 19.323,18.15 19.678,17.795 20.655,17.795 23.861,14.589 23.861,14.301 24.481,13.682 v1(24.481,13.6) ; v1(25.497,13.097) 26.392,12.202 26.392,6.818 26.55,6.66 v1(26.55,6.55)
  Layer2-Plane w0.152: v1(24.481,13.6) 24.5,13.6 24.989,13.111 25.483,13.111 v1(25.497,13.097)
  Layer3-Plane w0.152: v1(26.55,6.55) 27.22,7.22 29.35,7.22 29.929,6.641 29.929,4.541 J22.3@30.57,3.9
BBFET: J22.5 U1.48 | length 32.6
  Top Layer w0.152: U1.48@11.35,24.975 11.35,24.404 11.779,23.975 13.407,23.975 14.49,22.892 16.433,22.892 16.95,22.375 v1(16.95,21.675) ; v1(19.301,20.201) 19.167,20.067 19.167,19.215 19.957,18.425 20.887,18.425 26.696,12.616 26.696,7.285 27.382,6.6 v1(28.75,6.6)
  Layer2-Plane w0.152: v1(16.95,21.675) 18.422,20.203 19.299,20.203 v1(19.301,20.201)
  Layer3-Plane w0.152: v1(28.75,6.6) 28.75,6.49 28.671,6.411 28.671,4.529 J22.5@29.3,3.9
Bulk_OK: U1.47 U7.2 | length 23.8
  Top Layer w0.152: U1.47@11.85,24.975 11.85,26.327 11.929,26.405 11.929,27.3 12.208,27.579 12.208,28.531 12.58,28.904 23.271,28.904 24.875,27.3 28.925,27.3 29.85,26.375 U7.2@31.125,26.375
CR-BUS: J4.12 Q9.3 Q10.3 R44.2 U12.54 | length 21
  Top Layer w0.152: U12.54@77.875,17.05 78.89,17.05 79.35,17.51 v1(79.35,17.525) ; Q10.3@81.875,10.3 83.25,10.3 R44.2@84.175,9.375 84.175,9.525 v1(86.425,9.525) 86.4,9.55 86.4,10.4 Q9.3@86.375,10.425
  Bottom Layer w0.152: v1(79.35,17.525) 79.775,17.525 82.775,14.525 v1(82.775,10.3) ; J4.12@86.29,5.07 86.27,5.09 86.27,9.26 v1@86.425,9.415
CR_CFG1: Q9.1 U12.37 | length 14.2
  Top Layer w0.152: U12.37@74.425,8.6 74.44,8.615 74.44,9.815 74.833,10.208 75.867,10.208 77.9,8.175 79.05,8.175 80.175,7.05 84.65,7.05 85.425,7.825 Q9.1@85.425,8.025
CR_CFG2: Q10.1 U12.36 | length 9.6
  Top Layer w0.152: U12.36@73.925,8.6 73.935,8.61 73.935,9.835 74.613,10.513 76.037,10.513 77.725,8.825 79.575,8.825 80.176,8.224 80.707,8.224 80.925,8.006 Q10.1@80.925,7.95
DAC_LS: R66.2 R100.1 | length 25.7
  Top Layer w0.152: R100.1@44.575,25.2 44.475,25.2 43.65,24.375 43.65,20.427 44.452,19.625 v1(47.025,19.625) ; v1(57.875,10.575) 59.825,10.575 R66.2@59.85,10.6
  Bottom Layer w0.152: v1(47.025,19.625) 47.032,19.618 47.032,19.218 52.825,13.425 55.025,13.425 v1(57.875,10.575)
EXT_OVP_DIS: U12.78
FAN_FB: R107.1 U12.66 | length 2.5
  Top Layer w0.152: U12.66@73.425,22 73.425,23.263 73.625,23.463 R107.1@73.625,24.45
FAN_PWM: R112.2 U12.64 | length 2.7
  Top Layer w0.152: U12.64@74.425,22 74.425,24.037 74.514,24.126 74.601,24.126 74.825,24.35 R112.2@74.825,24.45
FAN_VFG: C68.2 J5.3 R107.2 | length 25.6
  Top Layer w0.152: v1(72.55,24.85) 72.55,24.96 72.792,25.202 72.792,25.218 72.9,25.326 73.401,25.326 73.625,25.55 C68.2@73.625,26.75
  Bottom Layer w0.152: v1(72.55,24.85) 72.581,24.85 72.842,25.112 91.963,25.112 92.55,24.525 J5.3@92.55,21.925
G_AC_I: C13.1 R23.1 U1.27 U3.6 | length 17.1
  Top Layer w0.152: U3.6@4.45,23.025 4.482,23.025 4.554,23.097 4.554,23.379 5.075,23.9 C13.1@5.175,23.9 ; U3.6@4.554,23.025 5.875,23.025 6.8,22.1 7.8,22.1 v1(8.158,21.742) ; v1(11.275,21.625) 11.275,21.075 12.145,20.205 12.626,20.205 13.689,19.142 v1(15.065,19.142) 15.647,19.142 15.838,19.333 16.421,19.333 16.604,19.15 U1.27@18.175,19.15
  Layer2-Plane w0.152: v1(8.158,21.742) 11.158,21.742 v1(11.275,21.625) ; v1(15.065,19.142) v1@15.065,19.242
GaN_Fault: J22.19 R21.2 | length 11.6
  Top Layer w0.152: v1(19.575,7.85) 19.275,7.55 19.275,4.375 19.621,4.029 20.281,4.029 J22.19@20.41,3.9 ; R21.2@24.3,7.5 24.524,7.276 24.524,6.826 v1@24.525,6.825
  Layer2-Plane w0.152: v1(19.575,7.85) 20.2,8.475 22.975,8.475 v1(24.525,6.925)
  Layer3-Plane w0.152: v1@24.456,6.894 v1@24.525,6.825
GaN_Fault_MCU: C9.2 R21.1 R22.2 R24.1 U1.32 | length 17.1
  Top Layer w0.152: U1.32@18.175,21.65 18.731,21.65 18.758,21.622 18.758,21.593 18.866,21.485 18.886,21.485 19.809,20.561 19.809,19.934 21.927,17.816 22.259,17.816 v1(22.3,17.775) ; v1(23.353,14.378) 23.771,13.96 23.771,10.629 24.3,10.1 C9.2@24.3,10 ; R21.1@24.3,8.7 C9.2@24.3,10 ; R22.2@25.4,10 C9.2@24.3,10
  Layer2-Plane w0.152: v1(22.3,17.775) 23.375,16.7 23.375,14.4 v1(23.353,14.378)
GaN_TMP: J22.17 R25.2 | length 15
  Top Layer w0.152: v1(9.6,6.7) R25.2@9.6,7.2
  Layer3-Plane w0.152: v1(9.6,6.7) 9.633,6.667 14.027,6.667 14.549,6.145 16.105,6.145 19.325,2.925 21.425,2.925 21.701,3.201 21.701,3.879 J22.17@21.68,3.9
GaN_TMP_MCU: C10.1 R25.1 R27.2 R104.2 | length 5.6
  Top Layer w0.152: R104.2@9.6,12.425 10.129,11.896 10.129,10.229 9.6,9.7 C10.1@9.6,9.6 R25.1@9.6,8.4 9.7,8.3 10.6,8.3 R27.2@10.7,8.4
HFFET_HS: J22.14 R17.2 U1.40 | length 28
  Top Layer w0.152: U1.40@15.35,24.975 15.354,24.971 15.354,23.829 v1(15.358,23.825) ; v1(18,16.3) 18,16.343 18.392,16.734 18.816,16.734 18.858,16.776 20.369,16.776 22.19,14.954 22.19,12.045 21.909,11.763 21.909,8.109 21.624,7.824 21.524,7.824 21.3,7.6 21.3,7.4 22.55,6.15 23.24,6.15 J22.14@24.22,5.17
  Layer2-Plane w0.152: v1(15.358,23.825) 15.358,22.913 14.785,22.339 14.785,21.002 16.054,19.733 16.58,19.733 18.555,17.758 18.555,16.855 v1(18,16.3)
HFFET_LS: J22.16 R18.2 U1.39 | length 25.9
  Top Layer w0.152: U1.39@15.85,24.975 15.85,24.025 v1(16.225,23.65) ; v1(19.6,16.268) 20.446,16.268 21.886,14.828 21.886,12.35 21.524,11.988 21.524,11.424 R18.2@21.3,11.2 21.3,11.1 20.55,10.35 20.55,7.025 21.075,6.5 21.769,6.5 22.95,5.319 J22.16@22.95,5.17
  Layer2-Plane w0.152: v1(16.225,23.65) 15.663,23.088 15.663,22.786 15.089,22.213 15.089,21.275 16.327,20.038 16.706,20.038 18.86,17.884 18.86,17.008 v1(19.6,16.268)
IAC_SNS: R9.2 R28.2 R36.2 U4.4 | length 7.5
  Top Layer w0.152: v1(1.5,23.575) R9.2@1.5,23.9 ; v1(2.075,22.068) 2.082,22.068 2.525,21.625 2.525,21.175 2.649,21.051 3.274,21.051 4.375,19.95 R28.2@4.375,19.85 4.35,19.85 4.25,19.75 4.474,19.526 5.174,19.526 5.6,19.1 R36.2@5.7,19.1
  Layer2-Plane w0.152: v1(1.5,23.575) 1.5,22.643 v1(2.075,22.068)
IMON: J6.5 R116.2 | length 12.2
  Top Layer w0.152: R116.2@65.425,4.6 65.649,4.376 65.649,2.392 65.975,2.066 v1(65.975,2)
  Bottom Layer w0.152: J6.5@58,3.8 58.063,3.737 58.063,3.101 58.482,2.681 62.356,2.681 62.7,3.025 64.95,3.025 v1(65.975,2)
iMon_EN: J4.16 U12.74 | length 28.5
  Top Layer w0.152: U12.74@69.425,22 69.475,21.95 69.475,20.6 v1(69.525,20.55)
  Bottom Layer w0.152: v1(69.525,20.55) 69.525,20.525 70.4,19.65 79.981,19.65 83.75,15.881 J4.16@83.75,5.07
iMon_Gain: J4.18 U12.59 | length 18.2
  Top Layer w0.152: U12.59@77.875,19.55 77.939,19.486 78.964,19.486 v1(79.35,19.1)
  Bottom Layer w0.152: v1(79.35,19.1) 80.1,19.1 83.445,15.755 83.445,6.035 J4.18@82.48,5.07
